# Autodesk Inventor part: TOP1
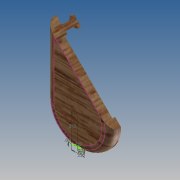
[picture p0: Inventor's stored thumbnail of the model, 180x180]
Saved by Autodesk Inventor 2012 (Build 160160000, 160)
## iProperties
Created: 2011-01
Part Number: TOP1
Document SubType Name: Modeling
Designer: Microsoft
Density: 1 g/cm^3
Material: Default
Author: Microsoft
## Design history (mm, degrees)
sketch "Sketch1"
  geometry: L1 (9.525, 0)-(9.525, 19.05); L2 (-9.525, 19.05)-(-9.525, 0); L3 (-9.525, 19.05)-(9.525, 0); A1 r 9.525 centre (0, 0) between (-9.525, 0) and (9.525, 0); A2 r 9.525 centre (0, 19.05) between (9.525, 19.05) and (-9.525, 19.05); 1 further point
  constraints: 6 end point, 4 point on circle, 3 tangent, 2 centre point, 1 coincident, 1 vertical alignment
  dimensions: "d3" = 9.525 radius of A2; "d4" = 9.525 radius of A1; "d5" = 19.05 distance of L1.start L1.end; "d6" = 19.05 distance of point (0, 0) A2.centre
extrude "Extrusion1" new body sketch "Sketch1" distance "d7" = 19.05; taper "d8" = 0 deg
workplane "Work Plane1"
sketch "Sketch7"
  geometry: L1 (-9.525, 19.05)-(9.525, 0) reference; L2 (-9.525, 0)-(-9.525, 19.05) reference; A1 r 9.525 centre (0, 0) between (-9.525, 0) and (9.525, 0) reference
extrude "Extrusion6" sketch "Sketch7" distance "d28" = 3.175; taper "d29" = 0 deg
fillet "Fillet1" dims "d37" = 2.54
sketch "Sketch11"
  geometry: L1 (9.525, 19.05)-(-9.525, 0); L2 (9.525, 19.05)-(5.951, 22.624); L3 (9.525, 19.05)-(-9.525, 0); L4 (7.841, 17.366)-(6.719, 16.244); A1 r 0.794 centre (7.28, 16.805) between (6.719, 16.244) and (7.841, 17.366)
  constraints: 8 end point, 3 point on line, 2 point on circle, 1 centre point, 1 collinear, 1 perpendicular
  dimensions: "d42" = 1.5875 diameter of A1; "d43" = 3.175 distance from line of L2 A1.centre
extrude "Extrusion10" join sketch "Sketch11" distance "d44" = 3.175; taper "d45" = 0 deg
sketch "Sketch12"
  geometry: L1 (7.28, 16.805)-(6.157, 15.682); L2 (6.719, 16.244)-(-9.525, 0) reference; L3 (7.28, 16.805)-(8.402, 17.927); L4 (9.525, 19.05)-(7.841, 17.366) reference; A1 r 0.794 centre (7.28, 16.805) between (6.719, 16.244) and (7.841, 17.366) reference; A2 r 1.587 centre (7.28, 16.805) between (6.157, 15.682) and (8.402, 17.927); 1 further point
  constraints: 4 end point, 2 point on circle, 2 point on line, 1 centre point, 1 coincident
  dimensions: "d46" = 3.175 diameter of A2
extrude "Extrusion11" join sketch "Sketch12" distance "d47" = 0.79375; taper "d48" = 0 deg
sketch "Sketch13"
  geometry: L1 (6.719, 16.244)-(-9.525, 0) reference; L2 (6.985, 0)-(9.525, 0) reference; L3 (7.938, 0)-(7.937, 15.36); A1 r 9.525 centre (0, 0) between (-9.525, 0) and (9.525, 0) reference; A2 r 7.938 centre (0, 0) between (-7.732, 1.793) and (7.938, 0); A3 r 1.587 centre (7.28, 16.805) between (6.157, 15.682) and (8.402, 17.927) reference
  constraints: 3 point on circle, 2 end point, 2 point on line, 1 centre point, 1 coincident, 1 perpendicular, 1 tangent
  dimensions: "d49" = 15.875 diameter of A2
extrude "Extrusion12" cut sketch "Sketch13" distance "d50" = 0.79375; taper "d51" = 0 deg
body "Solid1"
other parameters: "d17" = -6.35
